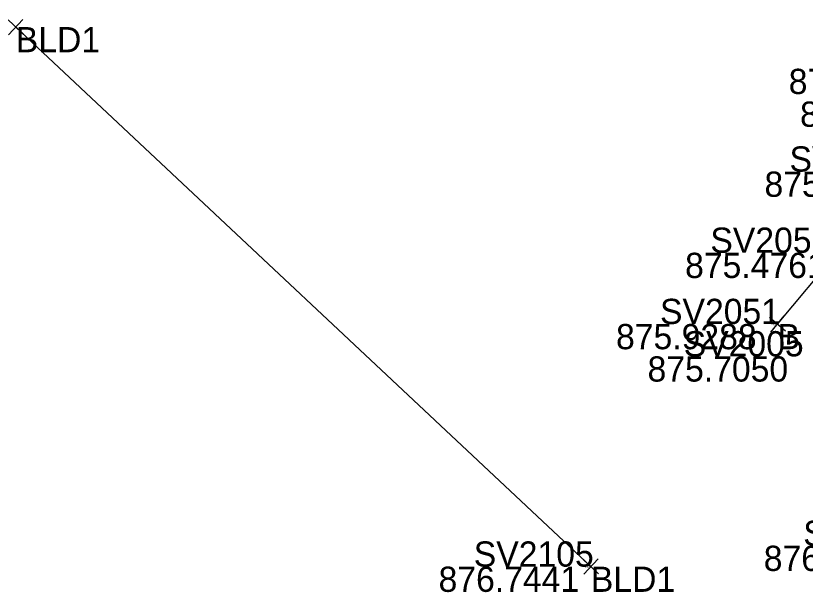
# Model space of a CAD drawing. Extents: x 1469677 to 1493262, y 375219 to 389293.
# Drawn here: x 1480042.74 to 1480080.32, y 379434.38 to 379461.81 of the extents above; entities that cross this region are included whole.
import ezdxf

# ---------------------------------------------------------------- set-up
doc = ezdxf.new("R2010")
doc.units = 0
for name, color, linetype in [('Border', 7, 'Continuous'), ('DV_X_Text', 7, 'Continuous'), ('GK_Visualization', 7, 'Continuous'), ('PNTELEV', 7, 'Continuous'), ('RW_P_Esmt_SW', 7, 'Continuous'), ('text', 7, 'Continuous')]:
    doc.layers.add(name, color=color, linetype=linetype)

msp = doc.modelspace()

# ---------------------------------------------------------------- linework, layer by layer
at = {"layer": 'Border'}
msp.add_lwpolyline([(1480070.116, 379435.596), (1480042.741, 379461.279)], dxfattribs=at)
at = {"layer": 'PNTELEV'}
for p, q in [((1480043.106, 379460.937), (1480042.376, 379461.621)), ((1480042.399, 379460.914), (1480043.083, 379461.644)), ((1480042.741, 379461.279), (1480042.741, 379461.279)), ((1480078.684, 379446.76), (1480079.326, 379447.527)), ((1480078.622, 379447.464), (1480079.388, 379446.823)), ((1480079.005, 379447.144), (1480079.005, 379447.144)), ((1480070.481, 379435.254), (1480069.751, 379435.938)), ((1480069.774, 379435.231), (1480070.458, 379435.961)), ((1480070.116, 379435.596), (1480070.116, 379435.596))]:
    msp.add_line(p, q, dxfattribs=at)
at = {"layer": 'text'}
msp.add_lwpolyline([(1480079.005, 379447.144), (1480081.842, 379450.534), (1480085.618, 379454.399), (1480087.323, 379457.733), (1480087.179, 379459.291), (1480084.148, 379463.202), (1480079.083, 379466.692), (1480077.899, 379467.657), (1480074.604, 379471.178), (1480070.008, 379471.999), (1480068.685, 379471.629)], dxfattribs=at)

# ---------------------------------------------------------------- texts
at = {"layer": 'DV_X_Text'}
for s, height, p in [('875.2755', 1.2, (1480079.535, 379458.091)), ('875.2331', 1.2, (1480080.074, 379456.533)), ('875.1493', 1.2, (1480078.381, 379453.199)), ('875.4761', 1.2, (1480074.602, 379449.334)), ('875.9288', 1.2, (1480071.314, 379445.944)), ('875.93', 0.06, (1480078.724, 379447.084)), ('875.7050', 1.2, (1480072.815, 379444.404)), ('876.0500', 1.2, (1480078.346, 379435.391)), ('876.7441', 1.2, (1480062.867, 379434.396)), ('876.74', 0.06, (1480069.836, 379435.536))]:
    msp.add_text(s, height=height, dxfattribs=at).set_placement(p)
at = {"layer": 'GK_Visualization'}
for s, p in [('BLD1', (1480042.741, 379460.079)), ('B', (1480079.005, 379445.944)), ('BLD1', (1480070.116, 379434.396))]:
    msp.add_text(s, height=1.2, dxfattribs=at).set_placement(p)
at = {"layer": 'RW_P_Esmt_SW'}
for s, height, p in [('SV2053', 1.2, (1480079.571, 379454.399)), ('SV2052', 1.2, (1480075.805, 379450.534)), ('SV2051', 1.2, (1480073.409, 379447.144)), ('SV2051', 0.06, (1480078.725, 379447.144)), ('SV2005', 1.2, (1480074.535, 379445.604)), ('SV2050', 1.2, (1480080.226, 379436.591)), ('SV2105', 1.2, (1480064.542, 379435.596)), ('SV2105', 0.06, (1480069.837, 379435.596))]:
    msp.add_text(s, height=height, dxfattribs=at).set_placement(p)

doc.saveas('drawing.dxf')
